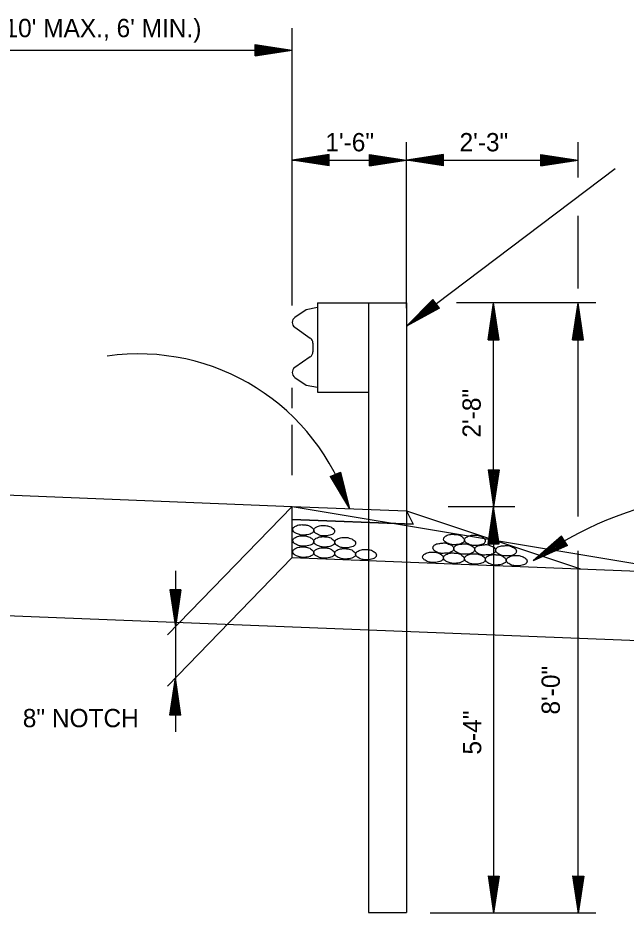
# Model space of a CAD drawing. Extents: x 1374136 to 1374281, y 380549 to 380948.
# Drawn here: x 1374228.33 to 1374248.28, y 380742.01 to 380771.37 of the extents above; entities that cross this region are included whole.
import ezdxf

# ---------------------------------------------------------------- set-up
doc = ezdxf.new("R2010")
doc.units = 0
doc.layers.add('Default', color=7, linetype='Continuous')
doc.layers.add('R_Draft', color=7, linetype='Continuous')

msp = doc.modelspace()

# ---------------------------------------------------------------- linework, layer by layer
at = {"layer": 'Default'}
for p, q in [((1374237.328, 380761.939), (1374237.328, 380771.042)), ((1374236.11, 380770.134), (1374236.111, 380770.5)), ((1374236.111, 380770.5), (1374237.328, 380770.317)), ((1374236.111, 380770.469), (1374237.124, 380770.317)), ((1374236.111, 380770.437), (1374236.915, 380770.317)), ((1374217.328, 380770.317), (1374237.328, 380770.317)), ((1374236.11, 380770.377), (1374236.507, 380770.318)), ((1374236.11, 380770.345), (1374236.302, 380770.318)), ((1374236.11, 380770.257), (1374236.507, 380770.318)), ((1374236.11, 380770.226), (1374236.711, 380770.318)), ((1374236.11, 380770.289), (1374236.302, 380770.318)), ((1374236.11, 380770.134), (1374237.328, 380770.317)), ((1374236.11, 380770.197), (1374236.915, 380770.317)), ((1374236.11, 380770.165), (1374237.124, 380770.317)), ((1374236.111, 380770.408), (1374236.711, 380770.318)), ((1374241.078, 380761.854), (1374241.078, 380767.298)), ((1374246.703, 380766.139), (1374246.703, 380767.298)), ((1374238.545, 380766.889), (1374237.328, 380766.706)), ((1374237.328, 380766.706), (1374241.078, 380766.706)), ((1374238.545, 380766.523), (1374237.328, 380766.706)), ((1374238.545, 380766.858), (1374237.532, 380766.706)), ((1374238.545, 380766.554), (1374237.532, 380766.706)), ((1374238.545, 380766.826), (1374237.741, 380766.706)), ((1374238.545, 380766.586), (1374237.741, 380766.706)), ((1374238.545, 380766.797), (1374237.945, 380766.707)), ((1374238.545, 380766.615), (1374237.945, 380766.707)), ((1374238.545, 380766.766), (1374238.149, 380766.707)), ((1374238.545, 380766.646), (1374238.149, 380766.707)), ((1374238.545, 380766.734), (1374238.353, 380766.707)), ((1374238.545, 380766.678), (1374238.353, 380766.707)), ((1374238.545, 380766.523), (1374238.545, 380766.889)), ((1374239.86, 380766.523), (1374239.861, 380766.889)), ((1374239.86, 380766.766), (1374240.257, 380766.707)), ((1374239.86, 380766.734), (1374240.052, 380766.707)), ((1374239.86, 380766.646), (1374240.257, 380766.707)), ((1374239.86, 380766.615), (1374240.461, 380766.707)), ((1374239.86, 380766.678), (1374240.052, 380766.707)), ((1374239.86, 380766.523), (1374241.078, 380766.706)), ((1374239.86, 380766.586), (1374240.665, 380766.706)), ((1374239.86, 380766.554), (1374240.874, 380766.706)), ((1374239.861, 380766.889), (1374241.078, 380766.706)), ((1374239.861, 380766.858), (1374240.874, 380766.706)), ((1374239.861, 380766.826), (1374240.665, 380766.706)), ((1374239.861, 380766.797), (1374240.461, 380766.707)), ((1374242.295, 380766.889), (1374241.078, 380766.706)), ((1374241.078, 380766.706), (1374246.703, 380766.706)), ((1374242.295, 380766.523), (1374241.078, 380766.706)), ((1374242.295, 380766.858), (1374241.282, 380766.706)), ((1374242.295, 380766.554), (1374241.282, 380766.706)), ((1374242.295, 380766.826), (1374241.491, 380766.706)), ((1374242.295, 380766.586), (1374241.491, 380766.706)), ((1374242.295, 380766.797), (1374241.695, 380766.707)), ((1374242.295, 380766.615), (1374241.695, 380766.707)), ((1374242.295, 380766.766), (1374241.899, 380766.707)), ((1374242.295, 380766.646), (1374241.899, 380766.707)), ((1374242.295, 380766.734), (1374242.103, 380766.707)), ((1374242.295, 380766.678), (1374242.103, 380766.707)), ((1374242.295, 380766.523), (1374242.295, 380766.889)), ((1374245.485, 380766.523), (1374245.486, 380766.889)), ((1374245.485, 380766.766), (1374245.882, 380766.707)), ((1374245.485, 380766.734), (1374245.677, 380766.707)), ((1374245.485, 380766.646), (1374245.882, 380766.707)), ((1374245.485, 380766.615), (1374246.086, 380766.707)), ((1374245.485, 380766.678), (1374245.677, 380766.707)), ((1374245.485, 380766.523), (1374246.703, 380766.706)), ((1374245.485, 380766.586), (1374246.29, 380766.706)), ((1374245.485, 380766.554), (1374246.499, 380766.706)), ((1374245.486, 380766.889), (1374246.703, 380766.706)), ((1374245.486, 380766.858), (1374246.499, 380766.706)), ((1374245.486, 380766.826), (1374246.29, 380766.706)), ((1374245.486, 380766.797), (1374246.086, 380766.707)), ((1374241.078, 380761.261), (1374247.923, 380766.435)), ((1374246.703, 380762.494), (1374246.703, 380764.886)), ((1374238.153, 380762.028), (1374241.078, 380762.028)), ((1374238.153, 380762.028), (1374238.153, 380759.103)), ((1374239.828, 380762.028), (1374239.828, 380742.028)), ((1374241.94, 380762.139), (1374241.078, 380761.261)), ((1374241.078, 380762.028), (1374241.078, 380742.028)), ((1374241.961, 380762.117), (1374241.239, 380761.382)), ((1374241.981, 380762.088), (1374241.412, 380761.514)), ((1374241.994, 380762.064), (1374241.572, 380761.634)), ((1374242.102, 380761.924), (1374241.572, 380761.634)), ((1374242.014, 380762.043), (1374241.733, 380761.757)), ((1374242.081, 380761.95), (1374241.733, 380761.757)), ((1374242.032, 380762.017), (1374241.897, 380761.881)), ((1374242.068, 380761.977), (1374241.897, 380761.881)), ((1374242.158, 380761.851), (1374241.94, 380762.139)), ((1374247.288, 380762.028), (1374242.717, 380762.028)), ((1374243.752, 380760.812), (1374243.935, 380762.028)), ((1374243.935, 380755.338), (1374243.935, 380762.028)), ((1374244.113, 380760.811), (1374243.935, 380762.028)), ((1374246.52, 380760.812), (1374246.703, 380762.028)), ((1374246.881, 380760.811), (1374246.703, 380762.028)), ((1374246.703, 380755.025), (1374246.703, 380762.028)), ((1374237.789, 380761.8), (1374237.413, 380761.548)), ((1374238.153, 380761.871), (1374237.789, 380761.8)), ((1374242.158, 380761.851), (1374241.078, 380761.261)), ((1374242.142, 380761.873), (1374241.239, 380761.382)), ((1374242.12, 380761.899), (1374241.412, 380761.514)), ((1374243.779, 380760.811), (1374243.933, 380761.827)), ((1374244.083, 380760.808), (1374243.933, 380761.827)), ((1374246.547, 380760.811), (1374246.701, 380761.827)), ((1374246.851, 380760.808), (1374246.701, 380761.827)), ((1374243.813, 380760.813), (1374243.934, 380761.61)), ((1374243.844, 380760.812), (1374243.933, 380761.409)), ((1374244.02, 380760.813), (1374243.933, 380761.409)), ((1374244.048, 380760.809), (1374243.934, 380761.61)), ((1374246.581, 380760.813), (1374246.702, 380761.61)), ((1374246.612, 380760.812), (1374246.701, 380761.409)), ((1374246.788, 380760.813), (1374246.701, 380761.409)), ((1374246.816, 380760.809), (1374246.702, 380761.61)), ((1374237.41, 380761.228), (1374237.922, 380760.869)), ((1374243.877, 380760.813), (1374243.934, 380761.207)), ((1374243.992, 380760.81), (1374243.934, 380761.207)), ((1374246.645, 380760.813), (1374246.702, 380761.207)), ((1374246.76, 380760.81), (1374246.702, 380761.207)), ((1374243.752, 380760.812), (1374244.113, 380760.811)), ((1374243.907, 380760.807), (1374243.933, 380761.002)), ((1374243.96, 380760.812), (1374243.933, 380761.002)), ((1374246.52, 380760.812), (1374246.881, 380760.811)), ((1374246.675, 380760.807), (1374246.702, 380761.002)), ((1374246.729, 380760.812), (1374246.702, 380761.002)), ((1374238.005, 380760.71), (1374238.005, 380760.566)), ((1374238.005, 380760.566), (1374238.005, 380760.422)), ((1374237.922, 380760.263), (1374237.41, 380759.904)), ((1374237.413, 380759.584), (1374237.789, 380759.332)), ((1374237.789, 380759.332), (1374238.153, 380759.261)), ((1374237.328, 380758.575), (1374237.328, 380759.24)), ((1374238.153, 380759.103), (1374239.828, 380759.103)), ((1374237.328, 380756.376), (1374237.328, 380758.026)), ((1374238.573, 380756.336), (1374238.911, 380756.476)), ((1374238.573, 380756.336), (1374239.203, 380755.278)), ((1374238.599, 380756.35), (1374239.126, 380755.468)), ((1374238.632, 380756.358), (1374239.047, 380755.663)), ((1374238.659, 380756.371), (1374238.972, 380755.847)), ((1374238.687, 380756.382), (1374238.893, 380756.04)), ((1374238.716, 380756.395), (1374238.813, 380756.227)), ((1374238.765, 380756.415), (1374238.813, 380756.227)), ((1374238.796, 380756.428), (1374238.893, 380756.04)), ((1374238.827, 380756.439), (1374238.972, 380755.847)), ((1374238.853, 380756.45), (1374239.047, 380755.663)), ((1374238.884, 380756.46), (1374239.126, 380755.468)), ((1374238.911, 380756.476), (1374239.203, 380755.278)), ((1374243.758, 380756.556), (1374243.935, 380755.338)), ((1374243.758, 380756.556), (1374244.12, 380756.555)), ((1374243.785, 380756.557), (1374243.934, 380755.54)), ((1374243.82, 380756.554), (1374243.936, 380755.757)), ((1374243.851, 380756.555), (1374243.937, 380755.957)), ((1374243.884, 380756.554), (1374243.938, 380756.16)), ((1374243.913, 380756.56), (1374243.939, 380756.365)), ((1374244.089, 380756.558), (1374243.934, 380755.54)), ((1374244.12, 380756.555), (1374243.935, 380755.338)), ((1374244.054, 380756.557), (1374243.936, 380755.757)), ((1374244.027, 380756.553), (1374243.937, 380755.957)), ((1374243.999, 380756.556), (1374243.938, 380756.16)), ((1374243.967, 380756.555), (1374243.939, 380756.365)), ((1374217.328, 380756.153), (1374237.328, 380755.353)), ((1374233.239, 380751.135), (1374237.328, 380755.353)), ((1374237.328, 380755.353), (1374241.078, 380755.203)), ((1374237.328, 380755.353), (1374273.2, 380749.375)), ((1374237.328, 380753.678), (1374237.328, 380755.353)), ((1374241.078, 380755.203), (1374246.788, 380753.3)), ((1374241.078, 380755.203), (1374241.295, 380754.77)), ((1374244.626, 380755.338), (1374242.448, 380755.338)), ((1374243.752, 380754.122), (1374243.935, 380755.338)), ((1374243.935, 380755.338), (1374243.935, 380742.013)), ((1374244.113, 380754.121), (1374243.935, 380755.338)), ((1374237.328, 380754.928), (1374241.295, 380754.77)), ((1374243.779, 380754.12), (1374243.933, 380755.137)), ((1374243.813, 380754.123), (1374243.934, 380754.92)), ((1374244.083, 380754.118), (1374243.933, 380755.137)), ((1374244.048, 380754.119), (1374243.934, 380754.92)), ((1374243.844, 380754.122), (1374243.933, 380754.719)), ((1374244.02, 380754.123), (1374243.933, 380754.719)), ((1374243.877, 380754.123), (1374243.934, 380754.517)), ((1374243.907, 380754.117), (1374243.933, 380754.312)), ((1374243.96, 380754.122), (1374243.933, 380754.312)), ((1374243.992, 380754.12), (1374243.934, 380754.517)), ((1374246.159, 380754.38), (1374245.236, 380753.565)), ((1374246.177, 380754.352), (1374245.408, 380753.674)), ((1374246.193, 380754.326), (1374245.583, 380753.789)), ((1374246.209, 380754.302), (1374245.752, 380753.9)), ((1374246.225, 380754.274), (1374245.924, 380754.011)), ((1374246.359, 380754.071), (1374246.159, 380754.38)), ((1374243.752, 380754.122), (1374244.113, 380754.121)), ((1374246.359, 380754.071), (1374245.236, 380753.565)), ((1374246.341, 380754.097), (1374245.408, 380753.674)), ((1374246.323, 380754.123), (1374245.583, 380753.789)), ((1374246.307, 380754.147), (1374245.752, 380753.9)), ((1374246.291, 380754.173), (1374245.924, 380754.011)), ((1374246.243, 380754.248), (1374246.099, 380754.122)), ((1374246.275, 380754.201), (1374246.099, 380754.122)), ((1374246.703, 380742.013), (1374246.703, 380753.898)), ((1374233.239, 380749.46), (1374237.328, 380753.678)), ((1374237.328, 380753.678), (1374250.552, 380753.15)), ((1374233.496, 380753.234), (1374233.496, 380747.958)), ((1374233.672, 380752.618), (1374233.311, 380752.617)), ((1374233.311, 380752.617), (1374233.496, 380751.4)), ((1374233.341, 380752.619), (1374233.496, 380751.601)), ((1374233.376, 380752.619), (1374233.494, 380751.819)), ((1374233.404, 380752.614), (1374233.494, 380752.019)), ((1374233.432, 380752.618), (1374233.492, 380752.221)), ((1374233.463, 380752.616), (1374233.491, 380752.426)), ((1374233.517, 380752.621), (1374233.491, 380752.426)), ((1374233.547, 380752.616), (1374233.492, 380752.221)), ((1374233.58, 380752.617), (1374233.494, 380752.019)), ((1374233.611, 380752.616), (1374233.494, 380751.819)), ((1374233.672, 380752.618), (1374233.496, 380751.4)), ((1374233.645, 380752.618), (1374233.496, 380751.601)), ((1374217.328, 380752.203), (1374268.512, 380750.156)), ((1374233.317, 380748.507), (1374233.496, 380749.725)), ((1374233.679, 380748.508), (1374233.496, 380749.725)), ((1374233.348, 380748.504), (1374233.497, 380749.523)), ((1374233.383, 380748.505), (1374233.496, 380749.306)), ((1374233.617, 380748.509), (1374233.496, 380749.306)), ((1374233.652, 380748.507), (1374233.497, 380749.523)), ((1374233.41, 380748.51), (1374233.497, 380749.106)), ((1374233.586, 380748.508), (1374233.497, 380749.106)), ((1374233.438, 380748.507), (1374233.497, 380748.903)), ((1374233.47, 380748.508), (1374233.497, 380748.698)), ((1374233.553, 380748.509), (1374233.497, 380748.903)), ((1374233.524, 380748.503), (1374233.497, 380748.698)), ((1374233.679, 380748.508), (1374233.317, 380748.507)), ((1374243.758, 380743.231), (1374243.935, 380742.013)), ((1374243.758, 380743.231), (1374244.12, 380743.23)), ((1374243.785, 380743.232), (1374243.934, 380742.215)), ((1374243.82, 380743.229), (1374243.936, 380742.432)), ((1374243.851, 380743.23), (1374243.937, 380742.632)), ((1374243.884, 380743.229), (1374243.938, 380742.835)), ((1374243.913, 380743.235), (1374243.939, 380743.04)), ((1374244.089, 380743.233), (1374243.934, 380742.215)), ((1374244.12, 380743.23), (1374243.935, 380742.013)), ((1374244.054, 380743.232), (1374243.936, 380742.432)), ((1374244.027, 380743.228), (1374243.937, 380742.632)), ((1374243.999, 380743.231), (1374243.938, 380742.835)), ((1374243.967, 380743.23), (1374243.939, 380743.04)), ((1374246.527, 380743.231), (1374246.703, 380742.013)), ((1374246.527, 380743.231), (1374246.888, 380743.23)), ((1374246.553, 380743.232), (1374246.702, 380742.215)), ((1374246.588, 380743.229), (1374246.704, 380742.432)), ((1374246.619, 380743.23), (1374246.705, 380742.632)), ((1374246.652, 380743.229), (1374246.707, 380742.835)), ((1374246.682, 380743.235), (1374246.707, 380743.04)), ((1374246.857, 380743.233), (1374246.702, 380742.215)), ((1374246.888, 380743.23), (1374246.703, 380742.013)), ((1374246.822, 380743.232), (1374246.704, 380742.432)), ((1374246.795, 380743.228), (1374246.705, 380742.632)), ((1374246.767, 380743.231), (1374246.707, 380742.835)), ((1374246.735, 380743.23), (1374246.707, 380743.04)), ((1374247.288, 380742.013), (1374241.852, 380742.013))]:
    msp.add_line(p, q, dxfattribs=at)
msp.add_lwpolyline([(1374237.328, 380754.928), (1374237.328, 380755.353), (1374241.078, 380755.203), (1374241.295, 380754.77)], close=True, dxfattribs=at)
for centre, radius, start, end in [((1374237.523, 380761.387), 0.195, 124.158, 234.7471), ((1374237.81, 380760.71), 0.195, 360, 54.7471), ((1374232.294, 380753.113), 7.24, 17.4027, 98.2159), ((1374237.81, 380760.422), 0.195, 305.2529, 0), ((1374237.523, 380759.745), 0.195, 125.2529, 235.842), ((1374252.238, 380743.793), 12.021, 73.3815, 125.6318)]:
    msp.add_arc(centre, radius, start, end, dxfattribs=at)
for points in [[(1374237.699, 380754.752), (1374237.579, 380754.75), (1374237.432, 380754.701), (1374237.362, 380754.637), (1374237.351, 380754.593), (1374237.386, 380754.52), (1374237.429, 380754.486), (1374237.505, 380754.448), (1374237.625, 380754.414), (1374237.683, 380754.409), (1374237.774, 380754.415), (1374237.873, 380754.432), (1374237.95, 380754.46), (1374238.02, 380754.517), (1374238.032, 380754.561), (1374238.011, 380754.626), (1374237.957, 380754.671), (1374237.906, 380754.708), (1374237.827, 380754.735), (1374237.776, 380754.747), (1374237.699, 380754.752)], [(1374238.385, 380754.724), (1374238.265, 380754.722), (1374238.118, 380754.674), (1374238.048, 380754.609), (1374238.037, 380754.566), (1374238.072, 380754.492), (1374238.115, 380754.459), (1374238.191, 380754.421), (1374238.311, 380754.386), (1374238.369, 380754.382), (1374238.46, 380754.388), (1374238.559, 380754.404), (1374238.636, 380754.432), (1374238.706, 380754.49), (1374238.718, 380754.533), (1374238.697, 380754.599), (1374238.643, 380754.644), (1374238.592, 380754.681), (1374238.513, 380754.708), (1374238.462, 380754.719), (1374238.385, 380754.724)], [(1374237.699, 380754.387), (1374237.579, 380754.385), (1374237.432, 380754.336), (1374237.362, 380754.272), (1374237.351, 380754.228), (1374237.386, 380754.155), (1374237.429, 380754.121), (1374237.505, 380754.083), (1374237.625, 380754.049), (1374237.683, 380754.044), (1374237.774, 380754.05), (1374237.873, 380754.067), (1374237.95, 380754.095), (1374238.02, 380754.152), (1374238.032, 380754.196), (1374238.011, 380754.261), (1374237.957, 380754.306), (1374237.906, 380754.343), (1374237.827, 380754.37), (1374237.776, 380754.382), (1374237.699, 380754.387)], [(1374238.385, 380754.359), (1374238.265, 380754.357), (1374238.118, 380754.309), (1374238.048, 380754.244), (1374238.037, 380754.201), (1374238.072, 380754.127), (1374238.115, 380754.094), (1374238.191, 380754.056), (1374238.311, 380754.021), (1374238.369, 380754.017), (1374238.46, 380754.023), (1374238.559, 380754.039), (1374238.636, 380754.067), (1374238.706, 380754.125), (1374238.718, 380754.168), (1374238.697, 380754.234), (1374238.643, 380754.279), (1374238.592, 380754.316), (1374238.513, 380754.343), (1374238.462, 380754.354), (1374238.385, 380754.359)], [(1374239.071, 380754.332), (1374238.951, 380754.33), (1374238.804, 380754.281), (1374238.734, 380754.217), (1374238.723, 380754.173), (1374238.758, 380754.1), (1374238.801, 380754.066), (1374238.877, 380754.029), (1374238.997, 380753.994), (1374239.055, 380753.989), (1374239.146, 380753.995), (1374239.245, 380754.012), (1374239.322, 380754.04), (1374239.392, 380754.097), (1374239.404, 380754.141), (1374239.383, 380754.207), (1374239.329, 380754.251), (1374239.279, 380754.288), (1374239.199, 380754.315), (1374239.148, 380754.327), (1374239.071, 380754.332)], [(1374242.643, 380754.436), (1374242.522, 380754.434), (1374242.376, 380754.386), (1374242.306, 380754.321), (1374242.294, 380754.278), (1374242.329, 380754.204), (1374242.373, 380754.171), (1374242.449, 380754.133), (1374242.568, 380754.098), (1374242.627, 380754.094), (1374242.718, 380754.1), (1374242.816, 380754.116), (1374242.893, 380754.144), (1374242.964, 380754.202), (1374242.975, 380754.245), (1374242.954, 380754.311), (1374242.9, 380754.356), (1374242.85, 380754.393), (1374242.77, 380754.42), (1374242.719, 380754.431), (1374242.643, 380754.436)], [(1374243.329, 380754.409), (1374243.209, 380754.407), (1374243.062, 380754.358), (1374242.992, 380754.294), (1374242.98, 380754.25), (1374243.015, 380754.177), (1374243.059, 380754.143), (1374243.135, 380754.106), (1374243.254, 380754.071), (1374243.313, 380754.066), (1374243.404, 380754.072), (1374243.503, 380754.089), (1374243.579, 380754.117), (1374243.65, 380754.174), (1374243.661, 380754.218), (1374243.64, 380754.284), (1374243.586, 380754.328), (1374243.536, 380754.366), (1374243.456, 380754.392), (1374243.405, 380754.404), (1374243.329, 380754.409)], [(1374237.699, 380754.022), (1374237.579, 380754.02), (1374237.432, 380753.971), (1374237.362, 380753.907), (1374237.351, 380753.863), (1374237.386, 380753.79), (1374237.429, 380753.756), (1374237.505, 380753.718), (1374237.625, 380753.684), (1374237.683, 380753.679), (1374237.774, 380753.685), (1374237.873, 380753.702), (1374237.95, 380753.73), (1374238.02, 380753.787), (1374238.032, 380753.831), (1374238.011, 380753.897), (1374237.957, 380753.941), (1374237.906, 380753.978), (1374237.827, 380754.005), (1374237.776, 380754.017), (1374237.699, 380754.022)], [(1374238.385, 380753.994), (1374238.265, 380753.992), (1374238.118, 380753.944), (1374238.048, 380753.879), (1374238.037, 380753.836), (1374238.072, 380753.762), (1374238.115, 380753.729), (1374238.191, 380753.691), (1374238.311, 380753.656), (1374238.369, 380753.652), (1374238.46, 380753.658), (1374238.559, 380753.674), (1374238.636, 380753.702), (1374238.706, 380753.76), (1374238.718, 380753.803), (1374238.697, 380753.869), (1374238.643, 380753.914), (1374238.592, 380753.951), (1374238.513, 380753.978), (1374238.462, 380753.989), (1374238.385, 380753.994)], [(1374242.299, 380754.153), (1374242.171, 380754.14), (1374242.028, 380754.106), (1374241.954, 380754.038), (1374241.943, 380753.998), (1374241.978, 380753.921), (1374242.021, 380753.887), (1374242.101, 380753.842), (1374242.217, 380753.811), (1374242.275, 380753.81), (1374242.366, 380753.816), (1374242.468, 380753.822), (1374242.546, 380753.857), (1374242.612, 380753.918), (1374242.624, 380753.965), (1374242.603, 380754.031), (1374242.549, 380754.076), (1374242.498, 380754.099), (1374242.419, 380754.133), (1374242.371, 380754.148), (1374242.299, 380754.153)], [(1374242.985, 380754.125), (1374242.857, 380754.113), (1374242.714, 380754.078), (1374242.64, 380754.01), (1374242.629, 380753.97), (1374242.664, 380753.893), (1374242.707, 380753.86), (1374242.787, 380753.815), (1374242.903, 380753.784), (1374242.961, 380753.783), (1374243.052, 380753.789), (1374243.155, 380753.795), (1374243.232, 380753.83), (1374243.298, 380753.891), (1374243.31, 380753.938), (1374243.289, 380754.004), (1374243.235, 380754.048), (1374243.184, 380754.071), (1374243.105, 380754.105), (1374243.058, 380754.12), (1374242.985, 380754.125)], [(1374243.671, 380754.098), (1374243.543, 380754.085), (1374243.4, 380754.051), (1374243.326, 380753.983), (1374243.315, 380753.943), (1374243.35, 380753.866), (1374243.393, 380753.832), (1374243.473, 380753.787), (1374243.589, 380753.756), (1374243.647, 380753.756), (1374243.738, 380753.761), (1374243.841, 380753.767), (1374243.918, 380753.802), (1374243.984, 380753.863), (1374243.996, 380753.911), (1374243.975, 380753.976), (1374243.921, 380754.021), (1374243.87, 380754.044), (1374243.791, 380754.078), (1374243.744, 380754.093), (1374243.671, 380754.098)], [(1374244.357, 380754.07), (1374244.229, 380754.058), (1374244.086, 380754.024), (1374244.012, 380753.955), (1374244.001, 380753.915), (1374244.036, 380753.838), (1374244.079, 380753.805), (1374244.159, 380753.76), (1374244.275, 380753.729), (1374244.333, 380753.728), (1374244.424, 380753.734), (1374244.527, 380753.74), (1374244.604, 380753.775), (1374244.67, 380753.836), (1374244.682, 380753.883), (1374244.661, 380753.949), (1374244.607, 380753.994), (1374244.556, 380754.016), (1374244.477, 380754.05), (1374244.43, 380754.066), (1374244.357, 380754.07)], [(1374239.071, 380753.967), (1374238.951, 380753.965), (1374238.804, 380753.916), (1374238.734, 380753.852), (1374238.723, 380753.808), (1374238.758, 380753.735), (1374238.801, 380753.701), (1374238.877, 380753.664), (1374238.997, 380753.629), (1374239.055, 380753.624), (1374239.146, 380753.63), (1374239.245, 380753.647), (1374239.322, 380753.675), (1374239.392, 380753.732), (1374239.404, 380753.776), (1374239.383, 380753.842), (1374239.329, 380753.886), (1374239.279, 380753.923), (1374239.199, 380753.95), (1374239.148, 380753.962), (1374239.071, 380753.967)], [(1374239.757, 380753.939), (1374239.637, 380753.938), (1374239.491, 380753.889), (1374239.42, 380753.824), (1374239.409, 380753.781), (1374239.444, 380753.707), (1374239.487, 380753.674), (1374239.563, 380753.636), (1374239.683, 380753.601), (1374239.741, 380753.597), (1374239.832, 380753.603), (1374239.931, 380753.619), (1374240.008, 380753.647), (1374240.078, 380753.705), (1374240.09, 380753.748), (1374240.069, 380753.814), (1374240.015, 380753.859), (1374239.965, 380753.896), (1374239.885, 380753.923), (1374239.834, 380753.934), (1374239.757, 380753.939)], [(1374241.954, 380753.851), (1374241.834, 380753.85), (1374241.687, 380753.801), (1374241.617, 380753.736), (1374241.605, 380753.693), (1374241.64, 380753.619), (1374241.684, 380753.586), (1374241.76, 380753.548), (1374241.879, 380753.514), (1374241.938, 380753.509), (1374242.029, 380753.515), (1374242.128, 380753.532), (1374242.205, 380753.56), (1374242.275, 380753.617), (1374242.286, 380753.66), (1374242.265, 380753.726), (1374242.211, 380753.771), (1374242.161, 380753.808), (1374242.081, 380753.835), (1374242.03, 380753.847), (1374241.954, 380753.851)], [(1374242.64, 380753.824), (1374242.52, 380753.822), (1374242.373, 380753.773), (1374242.303, 380753.709), (1374242.291, 380753.665), (1374242.326, 380753.592), (1374242.37, 380753.558), (1374242.446, 380753.521), (1374242.565, 380753.486), (1374242.624, 380753.482), (1374242.715, 380753.487), (1374242.814, 380753.504), (1374242.891, 380753.532), (1374242.961, 380753.589), (1374242.972, 380753.633), (1374242.951, 380753.699), (1374242.897, 380753.743), (1374242.847, 380753.781), (1374242.767, 380753.807), (1374242.716, 380753.819), (1374242.64, 380753.824)], [(1374243.326, 380753.797), (1374243.206, 380753.795), (1374243.059, 380753.746), (1374242.989, 380753.681), (1374242.977, 380753.638), (1374243.012, 380753.564), (1374243.056, 380753.531), (1374243.132, 380753.493), (1374243.251, 380753.459), (1374243.31, 380753.454), (1374243.401, 380753.46), (1374243.5, 380753.477), (1374243.577, 380753.505), (1374243.647, 380753.562), (1374243.658, 380753.605), (1374243.638, 380753.671), (1374243.584, 380753.716), (1374243.533, 380753.753), (1374243.453, 380753.78), (1374243.402, 380753.792), (1374243.326, 380753.797)], [(1374244.012, 380753.769), (1374243.892, 380753.767), (1374243.745, 380753.719), (1374243.675, 380753.654), (1374243.663, 380753.61), (1374243.699, 380753.537), (1374243.742, 380753.504), (1374243.818, 380753.466), (1374243.938, 380753.431), (1374243.996, 380753.427), (1374244.087, 380753.433), (1374244.186, 380753.449), (1374244.263, 380753.477), (1374244.333, 380753.534), (1374244.344, 380753.578), (1374244.324, 380753.644), (1374244.27, 380753.689), (1374244.219, 380753.726), (1374244.139, 380753.753), (1374244.088, 380753.764), (1374244.012, 380753.769)], [(1374244.698, 380753.742), (1374244.578, 380753.74), (1374244.431, 380753.691), (1374244.361, 380753.627), (1374244.349, 380753.583), (1374244.385, 380753.51), (1374244.428, 380753.476), (1374244.504, 380753.438), (1374244.624, 380753.404), (1374244.682, 380753.399), (1374244.773, 380753.405), (1374244.872, 380753.422), (1374244.949, 380753.45), (1374245.019, 380753.507), (1374245.03, 380753.551), (1374245.01, 380753.617), (1374244.956, 380753.661), (1374244.905, 380753.698), (1374244.825, 380753.725), (1374244.775, 380753.737), (1374244.698, 380753.742)]]:
    msp.add_spline(points, degree=3, dxfattribs=at)
at = {"layer": 'R_Draft'}
msp.add_line((1374239.828, 380742.028), (1374241.078, 380742.028), dxfattribs=at)

# ---------------------------------------------------------------- texts
at = {"layer": 'Default'}
for s, p in [("EXISTING SHOULDER (10' MAX., 6' MIN.)", (1374218.975, 380770.742)), ('1\'-6"', (1374238.415, 380766.998)), ('2\'-3"', (1374242.816, 380766.998)), ('8" NOTCH', (1374228.49, 380748.11))]:
    msp.add_text(s, height=0.6, dxfattribs=at).set_placement(p)
for s, p in [('2\'-8"', (1374243.512, 380757.609)), ('8\'-0"', (1374246.107, 380748.526)), ('5-4"', (1374243.529, 380747.213))]:
    msp.add_text(s, height=0.6, rotation=90, dxfattribs=at).set_placement(p)

doc.saveas('drawing.dxf')
